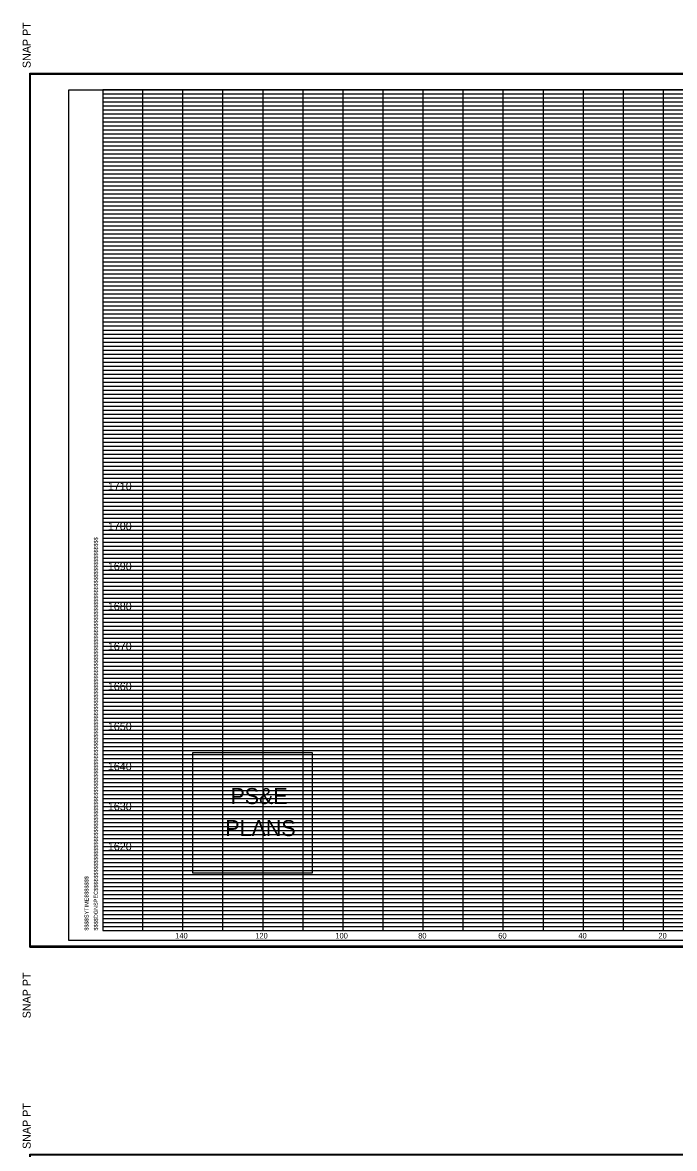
# Model space of a CAD drawing. Extents: x 980 to 2228, y 978 to 2394.
# Drawn here: x 979.9 to 1142.7, y 2025.5 to 2306.8 of the extents above; entities that cross this region are included whole.
import ezdxf

# ---------------------------------------------------------------- set-up
doc = ezdxf.new("R2010")
doc.units = 0
for name, color, linetype in [('DESIGN - SHEET - Corner Text', 7, 'Continuous'), ('DESIGN - SHEET - Light Grid', 7, 'Continuous'), ('DESIGN - SHEET - Linework', 7, 'Continuous'), ('DESIGN - SHEET - Plot Shape', 7, 'Continuous'), ('DESIGN - TYPICAL - Finished Grade and Subgrade', 7, 'Continuous')]:
    doc.layers.add(name, color=color, linetype=linetype)

# ---------------------------------------------------------------- blocks, each defined once
blk = doc.blocks.new('XSTSHT')
at = {"layer": 'DESIGN - SHEET - Light Grid'}
for p, q in [((0, 20.9), (8, 20.9)), ((8, 20.9), (16, 20.9)), ((0, 20.8), (8, 20.8)), ((0, 20.7), (8, 20.7)), ((0, 20.6), (8, 20.6)), ((8, 20.8), (16, 20.8)), ((8, 20.7), (16, 20.7)), ((8, 20.6), (16, 20.6)), ((0, 20.5), (8, 20.5)), ((0, 20.4), (8, 20.4)), ((0, 20.3), (8, 20.3)), ((8, 20.5), (16, 20.5)), ((8, 20.4), (16, 20.4)), ((8, 20.3), (16, 20.3)), ((0, 20.2), (8, 20.2)), ((0, 20.1), (8, 20.1)), ((8, 20.2), (16, 20.2)), ((8, 20.1), (16, 20.1)), ((0, 19.9), (8, 19.9)), ((0, 19.8), (8, 19.8)), ((0, 19.7), (8, 19.7)), ((8, 19.9), (16, 19.9)), ((8, 19.8), (16, 19.8)), ((8, 19.7), (16, 19.7)), ((0, 19.6), (8, 19.6)), ((0, 19.5), (8, 19.5)), ((8, 19.6), (16, 19.6)), ((8, 19.5), (16, 19.5)), ((0, 19.4), (8, 19.4)), ((0, 19.3), (8, 19.3)), ((0, 19.2), (8, 19.2)), ((8, 19.4), (16, 19.4)), ((8, 19.3), (16, 19.3)), ((8, 19.2), (16, 19.2)), ((0, 19.1), (8, 19.1)), ((0, 18.9), (8, 18.9)), ((8, 19.1), (16, 19.1)), ((8, 18.9), (16, 18.9)), ((0, 18.8), (8, 18.8)), ((0, 18.7), (8, 18.7)), ((0, 18.6), (8, 18.6)), ((8, 18.8), (16, 18.8)), ((8, 18.7), (16, 18.7)), ((8, 18.6), (16, 18.6)), ((0, 18.5), (8, 18.5)), ((0, 18.4), (8, 18.4)), ((0, 18.3), (8, 18.3)), ((8, 18.5), (16, 18.5)), ((8, 18.4), (16, 18.4)), ((8, 18.3), (16, 18.3)), ((0, 18.2), (8, 18.2)), ((0, 18.1), (8, 18.1)), ((8, 18.2), (16, 18.2)), ((8, 18.1), (16, 18.1)), ((0, 17.9), (8, 17.9)), ((0, 17.8), (8, 17.8)), ((8, 17.9), (16, 17.9)), ((8, 17.8), (16, 17.8)), ((0, 17.7), (8, 17.7)), ((0, 17.6), (8, 17.6)), ((0, 17.5), (8, 17.5)), ((8, 17.7), (16, 17.7)), ((8, 17.6), (16, 17.6)), ((8, 17.5), (16, 17.5)), ((0, 17.4), (8, 17.4)), ((0, 17.3), (8, 17.3)), ((0, 17.2), (8, 17.2)), ((8, 17.4), (16, 17.4)), ((8, 17.3), (16, 17.3)), ((8, 17.2), (16, 17.2)), ((0, 17.1), (8, 17.1)), ((0, 16.9), (8, 16.9)), ((8, 17.1), (16, 17.1)), ((8, 16.9), (16, 16.9)), ((0, 16.8), (8, 16.8)), ((0, 16.7), (8, 16.7)), ((0, 16.6), (8, 16.6)), ((8, 16.8), (16, 16.8)), ((8, 16.7), (16, 16.7)), ((8, 16.6), (16, 16.6)), ((0, 16.5), (8, 16.5)), ((0, 16.4), (8, 16.4)), ((8, 16.5), (16, 16.5)), ((8, 16.4), (16, 16.4)), ((0, 16.3), (8, 16.3)), ((0, 16.2), (8, 16.2)), ((0, 16.1), (8, 16.1)), ((8, 16.3), (16, 16.3)), ((8, 16.2), (16, 16.2)), ((8, 16.1), (16, 16.1)), ((0, 15.9), (8, 15.9)), ((0, 15.8), (8, 15.8)), ((8, 15.9), (16, 15.9)), ((8, 15.8), (16, 15.8)), ((0, 15.7), (8, 15.7)), ((0, 15.6), (8, 15.6)), ((0, 15.5), (8, 15.5)), ((8, 15.7), (16, 15.7)), ((8, 15.6), (16, 15.6)), ((8, 15.5), (16, 15.5)), ((0, 15.4), (8, 15.4)), ((0, 15.3), (8, 15.3)), ((0, 15.2), (8, 15.2)), ((8, 15.4), (16, 15.4)), ((8, 15.3), (16, 15.3)), ((8, 15.2), (16, 15.2)), ((0, 15.1), (8, 15.1)), ((8, 15.1), (16, 15.1)), ((0, 14.9), (8, 14.9)), ((0, 14.8), (8, 14.8)), ((0, 14.7), (8, 14.7)), ((8, 14.9), (16, 14.9)), ((8, 14.8), (16, 14.8)), ((8, 14.7), (16, 14.7)), ((0, 14.6), (8, 14.6)), ((0, 14.5), (8, 14.5)), ((0, 14.4), (8, 14.4)), ((8, 14.6), (16, 14.6)), ((8, 14.5), (16, 14.5)), ((8, 14.4), (16, 14.4)), ((0, 14.3), (8, 14.3)), ((0, 14.2), (8, 14.2)), ((0, 14.1), (8, 14.1)), ((8, 14.3), (16, 14.3)), ((8, 14.2), (16, 14.2)), ((8, 14.1), (16, 14.1)), ((0, 13.9), (8, 13.9)), ((0, 13.8), (8, 13.8)), ((8, 13.9), (16, 13.9)), ((8, 13.8), (16, 13.8)), ((0, 13.7), (8, 13.7)), ((0, 13.6), (8, 13.6)), ((8, 13.7), (16, 13.7)), ((8, 13.6), (16, 13.6)), ((0, 13.5), (8, 13.5)), ((0, 13.4), (8, 13.4)), ((0, 13.3), (8, 13.3)), ((8, 13.5), (16, 13.5)), ((8, 13.4), (16, 13.4)), ((8, 13.3), (16, 13.3)), ((0, 13.2), (8, 13.2)), ((0, 13.1), (8, 13.1)), ((8, 13.2), (16, 13.2)), ((8, 13.1), (16, 13.1)), ((0, 12.9), (8, 12.9)), ((0, 12.8), (8, 12.8)), ((0, 12.7), (8, 12.7)), ((8, 12.9), (16, 12.9)), ((8, 12.8), (16, 12.8)), ((8, 12.7), (16, 12.7)), ((0, 12.6), (8, 12.6)), ((0, 12.5), (8, 12.5)), ((0, 12.4), (8, 12.4)), ((8, 12.6), (16, 12.6)), ((8, 12.5), (16, 12.5)), ((8, 12.4), (16, 12.4)), ((0, 12.3), (8, 12.3)), ((0, 12.2), (8, 12.2)), ((0, 12.1), (8, 12.1)), ((8, 12.3), (16, 12.3)), ((8, 12.2), (16, 12.2)), ((8, 12.1), (16, 12.1)), ((0, 11.9), (8, 11.9)), ((8, 11.9), (16, 11.9)), ((0, 11.8), (8, 11.8)), ((0, 11.7), (8, 11.7)), ((0, 11.6), (8, 11.6)), ((8, 11.8), (16, 11.8)), ((8, 11.7), (16, 11.7)), ((8, 11.6), (16, 11.6)), ((0, 11.5), (8, 11.5)), ((0, 11.4), (8, 11.4)), ((0, 11.3), (8, 11.3)), ((8, 11.5), (16, 11.5)), ((8, 11.4), (16, 11.4)), ((8, 11.3), (16, 11.3)), ((0, 11.2), (8, 11.2)), ((0, 11.1), (8, 11.1)), ((8, 11.2), (16, 11.2)), ((8, 11.1), (16, 11.1)), ((0, 10.9), (8, 10.9)), ((0, 10.8), (8, 10.8)), ((0, 10.7), (8, 10.7)), ((8, 10.9), (16, 10.9)), ((8, 10.8), (16, 10.8)), ((8, 10.7), (16, 10.7)), ((0, 10.6), (8, 10.6)), ((0, 10.5), (8, 10.5)), ((8, 10.6), (16, 10.6)), ((8, 10.5), (16, 10.5)), ((0, 10.4), (8, 10.4)), ((0, 10.3), (8, 10.3)), ((0, 10.2), (8, 10.2)), ((8, 10.4), (16, 10.4)), ((8, 10.3), (16, 10.3)), ((8, 10.2), (16, 10.2)), ((0, 10.1), (8, 10.1)), ((0, 9.9), (8, 9.9)), ((8, 10.1), (16, 10.1)), ((8, 9.9), (16, 9.9)), ((0, 9.8), (8, 9.8)), ((0, 9.7), (8, 9.7)), ((0, 9.6), (8, 9.6)), ((8, 9.8), (16, 9.8)), ((8, 9.7), (16, 9.7)), ((8, 9.6), (16, 9.6)), ((0, 9.5), (8, 9.5)), ((0, 9.4), (8, 9.4)), ((0, 9.3), (8, 9.3)), ((8, 9.5), (16, 9.5)), ((8, 9.4), (16, 9.4)), ((8, 9.3), (16, 9.3)), ((0, 9.2), (8, 9.2)), ((0, 9.1), (8, 9.1)), ((8, 9.2), (16, 9.2)), ((8, 9.1), (16, 9.1)), ((0, 8.9), (8, 8.9)), ((0, 8.8), (8, 8.8)), ((8, 8.9), (16, 8.9)), ((8, 8.8), (16, 8.8)), ((0, 8.7), (8, 8.7)), ((0, 8.6), (8, 8.6)), ((0, 8.5), (8, 8.5)), ((8, 8.7), (16, 8.7)), ((8, 8.6), (16, 8.6)), ((8, 8.5), (16, 8.5)), ((0, 8.4), (8, 8.4)), ((0, 8.3), (8, 8.3)), ((0, 8.2), (8, 8.2)), ((8, 8.4), (16, 8.4)), ((8, 8.3), (16, 8.3)), ((8, 8.2), (16, 8.2)), ((0, 8.1), (8, 8.1)), ((0, 7.9), (8, 7.9)), ((8, 8.1), (16, 8.1)), ((8, 7.9), (16, 7.9)), ((0, 7.8), (8, 7.8)), ((0, 7.7), (8, 7.7)), ((0, 7.6), (8, 7.6)), ((8, 7.8), (16, 7.8)), ((8, 7.7), (16, 7.7)), ((8, 7.6), (16, 7.6)), ((0, 7.5), (8, 7.5)), ((0, 7.4), (8, 7.4)), ((8, 7.5), (16, 7.5)), ((8, 7.4), (16, 7.4)), ((0, 7.3), (8, 7.3)), ((0, 7.2), (8, 7.2)), ((0, 7.1), (8, 7.1)), ((8, 7.3), (16, 7.3)), ((8, 7.2), (16, 7.2)), ((8, 7.1), (16, 7.1)), ((0, 6.9), (8, 6.9)), ((0, 6.8), (8, 6.8)), ((8, 6.9), (16, 6.9)), ((8, 6.8), (16, 6.8)), ((0, 6.7), (8, 6.7)), ((0, 6.6), (8, 6.6)), ((0, 6.5), (8, 6.5)), ((8, 6.7), (16, 6.7)), ((8, 6.6), (16, 6.6)), ((8, 6.5), (16, 6.5)), ((0, 6.4), (8, 6.4)), ((0, 6.3), (8, 6.3)), ((0, 6.2), (8, 6.2)), ((8, 6.4), (16, 6.4)), ((8, 6.3), (16, 6.3)), ((8, 6.2), (16, 6.2)), ((0, 6.1), (8, 6.1)), ((8, 6.1), (16, 6.1)), ((0, 5.9), (8, 5.9)), ((0, 5.8), (8, 5.8)), ((0, 5.7), (8, 5.7)), ((8, 5.9), (16, 5.9)), ((8, 5.8), (16, 5.8)), ((8, 5.7), (16, 5.7)), ((0, 5.6), (8, 5.6)), ((0, 5.5), (8, 5.5)), ((0, 5.4), (8, 5.4)), ((8, 5.6), (16, 5.6)), ((8, 5.5), (16, 5.5)), ((8, 5.4), (16, 5.4)), ((0, 5.3), (8, 5.3)), ((0, 5.2), (8, 5.2)), ((0, 5.1), (8, 5.1)), ((8, 5.3), (16, 5.3)), ((8, 5.2), (16, 5.2)), ((8, 5.1), (16, 5.1)), ((0, 4.9), (8, 4.9)), ((0, 4.8), (8, 4.8)), ((8, 4.9), (16, 4.9)), ((8, 4.8), (16, 4.8)), ((0, 4.7), (8, 4.7)), ((0, 4.6), (8, 4.6)), ((8, 4.7), (16, 4.7)), ((8, 4.6), (16, 4.6)), ((0, 4.5), (8, 4.5)), ((0, 4.4), (8, 4.4)), ((0, 4.3), (8, 4.3)), ((8, 4.5), (16, 4.5)), ((8, 4.4), (16, 4.4)), ((8, 4.3), (16, 4.3)), ((0, 4.2), (8, 4.2)), ((0, 4.1), (8, 4.1)), ((8, 4.2), (16, 4.2)), ((8, 4.1), (16, 4.1)), ((0, 3.9), (8, 3.9)), ((0, 3.8), (8, 3.8)), ((0, 3.7), (8, 3.7)), ((8, 3.9), (16, 3.9)), ((8, 3.8), (16, 3.8)), ((8, 3.7), (16, 3.7)), ((0, 3.6), (8, 3.6)), ((0, 3.5), (8, 3.5)), ((0, 3.4), (8, 3.4)), ((8, 3.6), (16, 3.6)), ((8, 3.5), (16, 3.5)), ((8, 3.4), (16, 3.4)), ((0, 3.3), (8, 3.3)), ((0, 3.2), (8, 3.2)), ((0, 3.1), (8, 3.1)), ((8, 3.3), (16, 3.3)), ((8, 3.2), (16, 3.2)), ((8, 3.1), (16, 3.1)), ((0, 2.9), (8, 2.9)), ((8, 2.9), (16, 2.9)), ((0, 2.8), (8, 2.8)), ((0, 2.7), (8, 2.7)), ((0, 2.6), (8, 2.6)), ((8, 2.8), (16, 2.8)), ((8, 2.7), (16, 2.7)), ((8, 2.6), (16, 2.6)), ((0, 2.5), (8, 2.5)), ((0, 2.4), (8, 2.4)), ((0, 2.3), (8, 2.3)), ((8, 2.5), (16, 2.5)), ((8, 2.4), (16, 2.4)), ((8, 2.3), (16, 2.3)), ((0, 2.2), (8, 2.2)), ((0, 2.1), (8, 2.1)), ((8, 2.2), (16, 2.2)), ((8, 2.1), (16, 2.1)), ((0, 1.9), (8, 1.9)), ((0, 1.8), (8, 1.8)), ((0, 1.7), (8, 1.7)), ((8, 1.9), (16, 1.9)), ((8, 1.8), (16, 1.8)), ((8, 1.7), (16, 1.7)), ((0, 1.6), (8, 1.6)), ((0, 1.5), (8, 1.5)), ((8, 1.6), (16, 1.6)), ((8, 1.5), (16, 1.5)), ((0, 1.4), (8, 1.4)), ((0, 1.3), (8, 1.3)), ((0, 1.2), (8, 1.2)), ((8, 1.4), (16, 1.4)), ((8, 1.3), (16, 1.3)), ((8, 1.2), (16, 1.2)), ((0, 1.1), (8, 1.1)), ((0, 0.9), (8, 0.9)), ((8, 1.1), (16, 1.1)), ((8, 0.9), (16, 0.9)), ((0, 0.8), (8, 0.8)), ((0, 0.7), (8, 0.7)), ((0, 0.6), (8, 0.6)), ((8, 0.8), (16, 0.8)), ((8, 0.7), (16, 0.7)), ((8, 0.6), (16, 0.6)), ((0, 0.5), (8, 0.5)), ((0, 0.4), (8, 0.4)), ((0, 0.3), (8, 0.3)), ((8, 0.5), (16, 0.5)), ((8, 0.4), (16, 0.4)), ((8, 0.3), (16, 0.3)), ((0, 0.2), (8, 0.2)), ((0, 0.1), (8, 0.1)), ((8, 0.2), (16, 0.2)), ((8, 0.1), (16, 0.1))]:
    blk.add_line(p, q, dxfattribs=at)
at = {"layer": 'DESIGN - SHEET - Linework'}
for p, q in [((-1.823, -0.414), (-1.823, 21.414)), ((-1.823, 21.414), (32.217, 21.414)), ((1, 0), (1, 21)), ((2, 0), (2, 21)), ((3, 0), (3, 21)), ((4, 0), (4, 21)), ((5, 0), (5, 21)), ((6, 0), (6, 21)), ((7, 0), (7, 21)), ((8, 0), (8, 21)), ((9, 0), (9, 21)), ((10, 0), (10, 21)), ((11, 0), (11, 21)), ((12, 0), (12, 21)), ((13, 0), (13, 21)), ((14, 0), (14, 21)), ((0, 20), (28, 20)), ((0, 19), (32, 19)), ((0, 18), (32, 18)), ((0, 17), (32, 17)), ((0, 16), (32, 16)), ((0, 15), (32, 15)), ((0, 14), (32, 14)), ((0, 13), (32, 13)), ((0, 12), (32, 12)), ((0, 11), (32, 11)), ((0, 10), (32, 10)), ((0, 9), (32, 9)), ((0, 8), (32, 8)), ((0, 7), (32, 7)), ((0, 6), (32, 6)), ((0, 5), (32, 5)), ((0, 4), (32, 4)), ((0, 3), (32, 3)), ((0, 2), (32, 2)), ((0, 1), (32, 1)), ((-1.823, -0.414), (32.217, -0.414))]:
    blk.add_line(p, q, dxfattribs=at)
blk.add_lwpolyline([(0, 21), (0, 0), (32, 0), (32, 21), (0, 21)], dxfattribs=at)
at = {"layer": 'DESIGN - SHEET - Plot Shape'}
for points in [[(-1.803, 21.394), (32.197, 21.394), (32.197, -0.394), (-1.803, -0.394)], [(-0.85, 21), (32, 21), (32, -0.25), (-0.85, -0.25)]]:
    blk.add_lwpolyline(points, close=True, dxfattribs=at)
at = {"layer": 'DESIGN - SHEET - Corner Text'}
for s, height, p in [('  SNAP PT', 0.2, (-1.803, 21.394)), ('$$$$DGNSPEC$$$$$$$$$$$$$$$$$$$$$$$$$$$$$$$$$$$$$$$$$$$$$$$$$$$$$$$$$$$$$$$$$$$$$$$$$$$$$$$$$$$$$$$$$$$$$$$$$$$$$$$$$$$$$$$$$$$', 0.100002, (-0.126, 0)), ('$$$$SYTIME$$$$$$$', 0.1, (-0.358, 0)), ('SNAP PT  ', 0.2, (-1.803, -2.194))]:
    blk.add_text(s, height=height, rotation=90, dxfattribs=at).set_placement(p)

msp = doc.modelspace()

# ---------------------------------------------------------------- linework, layer by layer
at = {"layer": 'DESIGN - SHEET - Corner Text'}
msp.add_lwpolyline([(1022.35, 2124.41), (1022.35, 2094.41), (1052.35, 2094.41), (1052.35, 2124.41)], close=True, dxfattribs=at)
at = {"layer": 'DESIGN - SHEET - Plot Shape'}
msp.add_lwpolyline([(991.5, 2290), (1320, 2290), (1320, 2077.5), (991.5, 2077.5)], close=True, dxfattribs=at)

# ---------------------------------------------------------------- block references
at = {"layer": 'DESIGN - TYPICAL - Finished Grade and Subgrade', "xscale": 10, "yscale": 10}
for p in [(1000, 2080), (1000, 1810)]:
    msp.add_blockref('XSTSHT', p, dxfattribs=at)

# ---------------------------------------------------------------- texts
at = {"layer": 'DESIGN - SHEET - Corner Text'}
for s, height, p in [('1710', 2, (1001.25, 2190)), ('1700', 2, (1001.25, 2180)), ('1690', 2, (1001.25, 2170)), ('1680', 2, (1001.25, 2160)), ('1670', 2, (1001.25, 2150)), ('1660', 2, (1001.25, 2140)), ('1650', 2, (1001.25, 2130)), ('1640', 2, (1001.25, 2120)), ('PS&E', 4, (1031.87, 2111.58)), ('1630', 2, (1001.25, 2110)), ('PLANS', 4, (1030.59, 2103.58)), ('1620', 2, (1001.25, 2100)), ('140', 1.4, (1018.06, 2078)), ('120', 1.4, (1038.06, 2078)), ('100', 1.4, (1058.06, 2078)), ('80', 1.4, (1078.74, 2078)), ('60', 1.4, (1098.74, 2078)), ('40', 1.4, (1118.74, 2078)), ('20', 1.4, (1138.74, 2078))]:
    msp.add_text(s, height=height, dxfattribs=at).set_placement(p)

doc.saveas('drawing.dxf')
